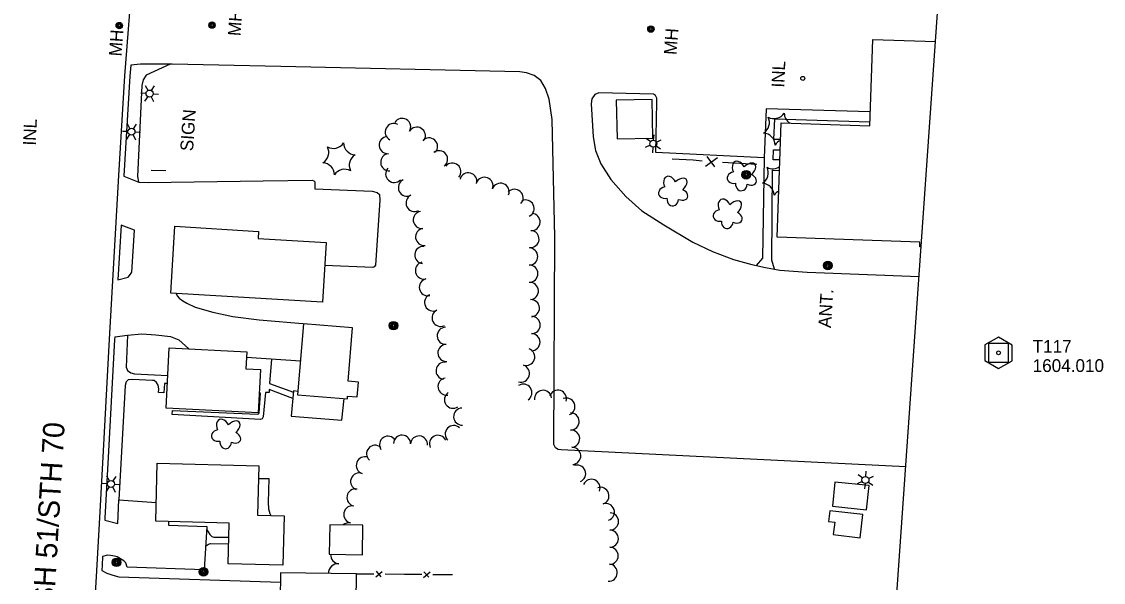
# Model space of a CAD drawing. Extents: x 189384 to 193282, y 256970 to 260388.
# Drawn here: x 190988 to 191495, y 259610 to 259872 of the extents above; entities that cross this region are included whole.
import ezdxf

# ---------------------------------------------------------------- set-up
doc = ezdxf.new("R2010")
doc.units = 0
for name, color, linetype in [('E_DRN_Grate', 7, 'Continuous'), ('E_DWY', 7, 'Continuous'), ('E_LAND_Vegetation', 7, 'Continuous'), ('E_MAP_Control', 7, 'Continuous'), ('E_MAP_Limits', 7, 'Continuous'), ('E_MISCPROP', 7, 'Continuous'), ('E_MISCPROP_HvyLine', 7, 'Continuous'), ('E_MISCPROP_Railing', 7, 'Continuous'), ('E_PATH_Sidewalk', 7, 'Continuous'), ('E_RDWY', 7, 'Continuous'), ('E_RDWY_Name', 7, 'Continuous')]:
    doc.layers.add(name, color=color, linetype=linetype)

# ---------------------------------------------------------------- blocks, each defined once
blk = doc.blocks.new('TP')
at = {"layer": 'E_MAP_Control'}
for points in [[(-6.41, 3.76), (-6.41, -3.63), (0.05, -7.35), (6.44, -3.69), (6.44, 3.64), (-0.08, 7.36)], [(-4.5, -4.5), (-4.5, 4.5), (4.5, 4.5), (4.5, -4.5)]]:
    blk.add_lwpolyline(points, close=True, dxfattribs=at)
blk.add_circle((0, 0), 0.871, dxfattribs=at)
blk = doc.blocks.new('INL_3')
at = {"layer": 'E_MISCPROP_Railing'}
blk.add_text('INL', height=6, rotation=0.0001, dxfattribs=at).set_placement((-5.79, -2.75))
blk = doc.blocks.new('MHO')
at = {"layer": 'E_DRN_Grate'}
for centre, radius in [((0.04, -0.06), 1.5), ((0.04, -0.06), 1.22), ((0.04, -0.07), 0.968), ((0.01, -0.08), 0.605)]:
    blk.add_circle(centre, radius, dxfattribs=at)
blk = doc.blocks.new('MHO_1')
at = {"layer": 'E_DRN_Grate'}
for centre, radius in [((0.04, -0.06), 1.5), ((0.04, -0.06), 1.22), ((0.04, -0.07), 0.968), ((0.01, -0.08), 0.605)]:
    blk.add_circle(centre, radius, dxfattribs=at)
blk = doc.blocks.new('MHO_2')
at = {"layer": 'E_DRN_Grate'}
for centre, radius in [((0.04, -0.06), 1.5), ((0.04, -0.06), 1.22), ((0.04, -0.07), 0.968), ((0.01, -0.08), 0.605)]:
    blk.add_circle(centre, radius, dxfattribs=at)
blk = doc.blocks.new('MHT')
at = {"layer": 'E_DRN_Grate'}
blk.add_text('MH', height=6, rotation=0.0001, dxfattribs=at).set_placement((-5.61, -3.06))
blk = doc.blocks.new('POLE')
at = {"layer": 'E_MISCPROP'}
for radius in [2.02, 1.51, 1.01, 0.504]:
    blk.add_circle((0.03, -0.09), radius, dxfattribs=at)
blk = doc.blocks.new('LTP')
at = {"layer": 'E_MISCPROP'}
for p, q in [((-1.61, 0.09), (-4.22, 0.17)), ((-0.78, 1.46), (-1.98, 3.76)), ((0.86, 1.37), (2.22, 3.6)), ((1.66, 0), (4.18, -0.06)), ((-0.86, -1.4), (-2.22, -3.59)), ((0.78, -1.44), (2.02, -3.62))]:
    blk.add_line(p, q, dxfattribs=at)
blk.add_circle((0.02, 0.01), 1.64, dxfattribs=at)
blk = doc.blocks.new('ANT')
at = {"layer": 'E_MISCPROP'}
blk.add_text('ANT.', height=6, rotation=359.9999, dxfattribs=at).set_placement((0, -2.05))
blk = doc.blocks.new('LTP_1')
at = {"layer": 'E_MISCPROP'}
for p, q in [((-1.61, 0.09), (-4.22, 0.17)), ((-0.78, 1.46), (-1.98, 3.76)), ((0.86, 1.37), (2.22, 3.6)), ((1.66, 0), (4.18, -0.07)), ((-0.86, -1.4), (-2.22, -3.59)), ((0.78, -1.44), (2.02, -3.62))]:
    blk.add_line(p, q, dxfattribs=at)
blk.add_circle((0.02, 0.01), 1.64, dxfattribs=at)
blk = doc.blocks.new('POLE_1')
at = {"layer": 'E_MISCPROP'}
for radius in [2.02, 1.51, 1.01, 0.504]:
    blk.add_circle((0.03, -0.09), radius, dxfattribs=at)
blk = doc.blocks.new('LTP_2')
at = {"layer": 'E_MISCPROP'}
for p, q in [((-1.63, 0.07), (-4.24, 0.14)), ((-0.8, 1.43), (-2, 3.73)), ((0.9, 1.42), (2.27, 3.65)), ((-0.88, -1.42), (-2.24, -3.61)), ((0.76, -1.47), (2, -3.65)), ((1.64, -0.02), (4.16, -0.09))]:
    blk.add_line(p, q, dxfattribs=at)
blk.add_circle((0, 0), 1.64, dxfattribs=at)
blk = doc.blocks.new('TREE')
at = {"layer": 'E_LAND_Vegetation'}
for centre, major_axis, ratio in [((-1.07, 3.38), (0.91, -3.32), 0.782863), ((2.88, 1.66), (-3.52, -1.95), 0.691916), ((-3.74, -0.07), (3.29, -0.08), 0.832022), ((-1.48, -3.66), (1.2, 3.24), 0.716896), ((2.54, -2.64), (-3.34, 3.06), 0.560249)]:
    blk.add_ellipse(centre, major_axis=major_axis, ratio=ratio, start_param=1.570796, end_param=4.712389, dxfattribs=at)
blk = doc.blocks.new('PINEL')
at = {"layer": 'E_LAND_Vegetation'}
for centre, start, end in [((-8.23, 7.26), 275.2112, 0.9761), ((2.17, 10.66), 215.2112, 300.9761), ((10.31, 3.35), 155.2112, 240.9761), ((-10.49, -3.45), 335.2112, 60.9761), ((-2.35, -10.75), 35.2112, 120.9761), ((8.05, -7.36), 95.2112, 180.9761)]:
    blk.add_arc(centre, 5.72, start, end, dxfattribs=at)
blk = doc.blocks.new('SIGN')
at = {"layer": 'E_MISCPROP'}
blk.add_text('SIGN', height=6, rotation=0, dxfattribs=at).set_placement((0, -3))

msp = doc.modelspace()

# ---------------------------------------------------------------- linework, layer by layer
at = {"layer": 'E_DWY'}
for points in [[(191402.16, 259663.69), (191240.53, 259671.73), (191239.13, 259671.9), (191237.9, 259672.67), (191237.12, 259674.14), (191237.58, 259771.33), (191236.28, 259826.49), (191234.96, 259836.07), (191233.23, 259841.02), (191231.09, 259844.77), (191227.98, 259847.13), (191224.37, 259848.5), (191221.13, 259848.96), (191109.06, 259851.37), (191058.14, 259852.46), (191048.81, 259852.54), (191043.28, 259852.44), (191038.79, 259851.99)], [(191385.51, 259830.13), (191336.64, 259831.54), (191335.82, 259808.53), (191284.99, 259811.01), (191285.48, 259834.58), (191285.45, 259836.62), (191284.77, 259837.8), (191283.85, 259838.37), (191258.15, 259839.12), (191256.33, 259838.31), (191254.97, 259836.3), (191254.66, 259833.87), (191255.6, 259818.44), (191256.65, 259812.04), (191259.22, 259805.71), (191263.92, 259798.38), (191270.86, 259790.38), (191278.41, 259783.8), (191288.72, 259777.17), (191302.23, 259768.99), (191311.48, 259764.68), (191321.42, 259760.85), (191329.92, 259758.51), (191336.36, 259757.24), (191343.02, 259755.98)], [(191035.55, 259799.93), (191042.48, 259797.24), (191046.87, 259796.96), (191100.77, 259797.79), (191123.76, 259798.06), (191124.65, 259797.84), (191125.13, 259797.37), (191125.04, 259794.02), (191152, 259793.01), (191154.24, 259792.4), (191155.35, 259791.33), (191155.57, 259788.73), (191153.47, 259758.33), (191152.89, 259757.48), (191152.26, 259757.21), (191129.67, 259758.13)], [(191032.76, 259751.36), (191037.57, 259752.69), (191038.7, 259754.03), (191039.2, 259755.02), (191040.52, 259774.72), (191034.23, 259776.97)], [(191343.02, 259755.98), (191355.92, 259755.03), (191408.39, 259752.89)], [(191060.1, 259745.06), (191060.53, 259743.85), (191061.42, 259742.84), (191063.12, 259741.6), (191065.04, 259740.52), (191068.91, 259738.59), (191077.2, 259736.23), (191086.61, 259734.26), (191098.98, 259732.68), (191121.36, 259730.71), (191121.35, 259730.59)], [(191031.23, 259724.68), (191037.25, 259725.5), (191043.9, 259726.06), (191050.56, 259725.68), (191057.33, 259724.8), (191061.25, 259723.23), (191066.03, 259719.03)], [(191118.28, 259713.24), (191093.01, 259715.03)], [(191117.12, 259699.11), (191115.05, 259699.3), (191114.01, 259687.49), (191137.76, 259685.63), (191138.82, 259695.71)], [(191026.54, 259638.67), (191032.68, 259637.22), (191033.21, 259648.18), (191050.7, 259647.05)], [(191056.52, 259638.06), (191056.42, 259636.38), (191074.39, 259635.78), (191073.13, 259615.36), (191037.04, 259616.68), (191036.43, 259618.74), (191035.47, 259619.68), (191033.94, 259620.64), (191032.41, 259621.53), (191031.14, 259621.86), (191029.29, 259622.22), (191027.9, 259622.25), (191025.56, 259621.74)], [(191025.18, 259615.09), (191027.52, 259613.84), (191030.43, 259612.99), (191033.12, 259612.2), (191108.93, 259609.72)]]:
    msp.add_lwpolyline(points, dxfattribs=at)
at = {"layer": 'E_LAND_Vegetation'}
for centre, radius, start, end in [((191340.34, 259832.7), 5.72, 241.2443, 327.0092), ((191350.86, 259829.71), 5.72, 181.2443, 237.4918), ((191162.08, 259820.66), 4.02, 62.7249, 242.7096), ((191166, 259823.08), 4.02, 329.1892, 149.1738), ((191172.91, 259818.96), 4.02, 329.1892, 149.1738), ((191332.48, 259825.08), 5.72, 301.2443, 27.0092), ((191159.27, 259814.53), 4.02, 94.8325, 274.8172), ((191178.62, 259813.91), 4.02, 317.9066, 137.8912), ((191335.15, 259814.47), 5.72, 1.2443, 87.0092), ((191345.68, 259811.48), 5.72, 112.992, 147.0092), ((191159.94, 259806.51), 4.02, 94.8325, 274.8172), ((191183.32, 259807.92), 4.02, 306.74, 126.7247), ((191162.29, 259801.03), 4.02, 137.6347, 317.6194), ((191189.52, 259802.12), 4.02, 319.8311, 139.8158), ((191332, 259801.54), 5.72, 301.2443, 27.0092), ((191339.85, 259809.16), 5.72, 241.2443, 303.3262), ((191168.24, 259794.65), 4.02, 116.4551, 296.4398), ((191197.01, 259797.56), 4.02, 344.5372, 164.5219), ((191204.59, 259795.45), 4.02, 339.6891, 159.6738), ((191212.14, 259792.66), 4.02, 339.6891, 159.6738), ((191218.72, 259789.82), 4.02, 317.857, 137.8417), ((191334.67, 259790.93), 5.72, 1.2443, 87.0092), ((191345.19, 259787.94), 5.72, 117.0334, 147.0092), ((191171.83, 259787.45), 4.02, 116.4551, 296.4398), ((191223.88, 259784.83), 4.02, 295.7329, 115.7176), ((191175.21, 259779.47), 4.02, 97.8465, 277.8311), ((191226.66, 259778.52), 4.02, 266.5729, 86.5575), ((191176.3, 259771.5), 4.02, 97.8465, 277.8311), ((191226.17, 259770.54), 4.02, 265.1936, 85.1783), ((191175.91, 259763.03), 4.02, 85.482, 265.4667), ((191225.59, 259762.32), 4.02, 270.5168, 90.5015), ((191176.21, 259755.73), 4.02, 103.0357, 283.0204), ((191225.67, 259754.28), 4.02, 270.5168, 90.5015), ((191178.03, 259747.89), 4.02, 103.0357, 283.0204), ((191225.88, 259746.13), 4.02, 273.47, 93.4547), ((191180.52, 259740.79), 4.02, 115.9365, 295.9212), ((191226.37, 259738.1), 4.02, 273.47, 93.4547), ((191184.04, 259733.56), 4.02, 115.9365, 295.9212), ((191226.74, 259730.22), 4.02, 269.279, 89.2637), ((191186.44, 259725.15), 4.02, 92.2292, 272.2139), ((191226.63, 259722.18), 4.02, 269.279, 89.2637), ((191186.76, 259717.12), 4.02, 92.2292, 272.2139), ((191224.18, 259715.25), 4.02, 250.5735, 70.5581), ((191185.89, 259708.79), 4.02, 83.1503, 263.135), ((191221.72, 259707.48), 4.02, 253.4973, 73.482), ((191186.8, 259701.36), 4.02, 97.9664, 277.9511), ((191222.85, 259698.48), 4.02, 303.885, 123.8697), ((191189.86, 259695.21), 4.02, 124.9042, 304.8888), ((191232.05, 259695.58), 4.02, 7.2639, 187.2485), ((191239.02, 259695.67), 4.02, 342.1272, 162.1119), ((191243.02, 259691.94), 4.02, 291.4519, 111.4366), ((191194.15, 259687.28), 4.02, 92.9775, 272.9622), ((191244.99, 259684.99), 4.02, 271.7369, 91.7215), ((191190.22, 259679.08), 4.02, 46.8247, 226.8094), ((191245.25, 259676.89), 4.02, 273.423, 93.4077), ((191159.4, 259674.08), 4.02, 32.6316, 212.6162), ((191165.95, 259674.56), 4.02, 358.2017, 178.1864), ((191173.87, 259674.18), 4.02, 355.0803, 175.065), ((191182.83, 259674.48), 4.02, 25.6409, 205.6255), ((191153.33, 259669.83), 4.02, 48.6161, 228.6008), ((191245.73, 259668.86), 4.02, 273.423, 93.4077), ((191148.53, 259664.42), 4.02, 70.5684, 250.5531), ((191145.85, 259656.83), 4.02, 70.5684, 250.5531), ((191248.06, 259660.55), 4.02, 292.1882, 112.1728), ((191254.76, 259653.87), 4.02, 337.0118, 156.9964), ((191144.12, 259649.33), 4.02, 79.4575, 259.4422), ((191258.97, 259650.11), 4.02, 288.6257, 108.6104), ((191142.62, 259641.41), 4.02, 78.9621, 258.9468), ((191261.53, 259642.49), 4.02, 288.6257, 108.6104), ((191263.44, 259638.11), 4.02, 269.4967, 89.4814), ((191141.08, 259633.51), 4.02, 78.9621, 132.3743), ((191263.37, 259630.07), 4.02, 269.4967, 89.4814), ((191263.29, 259622.02), 4.02, 269.4967, 89.4814), ((191136.85, 259622.58), 4.41, 178.2852, 263.623), ((191135.87, 259613.82), 4.41, 83.6383, 180.786), ((191262.87, 259614.12), 4.02, 265.9746, 85.9593)]:
    msp.add_arc(centre, radius, start, end, dxfattribs=at)
at = {"layer": 'E_MAP_Limits'}
msp.add_lwpolyline([(191355.32, 259180.1), (191395.97, 259575.08), (191425.78, 260001.74)], dxfattribs=at)
at = {"layer": 'E_MISCPROP'}
msp.add_line((191048.38, 259802.84), (191055.22, 259802.63), dxfattribs=at)
at = {"layer": 'E_MISCPROP_HvyLine'}
msp.add_lwpolyline([(191409.37, 259766.82), (191408.66, 259766.84), (191408.66, 259766.84), (191408.74, 259768.98), (191408.74, 259768.98), (191341.81, 259771.39), (191341.81, 259771.39), (191343.74, 259825.02), (191343.74, 259825.02), (191385.27, 259823.53), (191385.27, 259823.53), (191385.27, 259823.53), (191386.73, 259864.13), (191416.09, 259863.07)], dxfattribs=at)
for points in [[(191266.4, 259835.67), (191266.76, 259817.49), (191266.76, 259817.49), (191266.76, 259817.49), (191283.56, 259817.82), (191283.56, 259817.82), (191283.2, 259836), (191266.4, 259835.67)], [(191128.62, 259740.87), (191128.62, 259740.87), (191057.54, 259745.21), (191059.45, 259776.48), (191059.45, 259776.48), (191098.64, 259774.08), (191098.64, 259774.08), (191098.64, 259774.08), (191098.64, 259774.08), (191098.44, 259770.81), (191130.33, 259768.86), (191130.33, 259768.86), (191130.33, 259768.86)], [(191119.72, 259730.72), (191119.72, 259730.72), (191116.99, 259697.5), (191116.99, 259697.5), (191140.34, 259695.58), (191140.34, 259695.58), (191140.45, 259696.87), (191140.45, 259696.87), (191144.97, 259696.5), (191145.55, 259703.46), (191145.55, 259703.46), (191140.71, 259703.86), (191140.71, 259703.86), (191142.76, 259728.83), (191142.76, 259728.83), (191119.72, 259730.72)], [(191056.79, 259719.51), (191093.15, 259717.63), (191093.15, 259717.63), (191093.15, 259717.63), (191092.74, 259709.73), (191092.74, 259709.73), (191099.6, 259709.37), (191099.6, 259709.37), (191098.55, 259689.01), (191055.33, 259691.25), (191055.33, 259691.25), (191056.79, 259719.51)], [(191050.48, 259638.21), (191050.48, 259638.21), (191051.16, 259665.44), (191051.16, 259665.44), (191098.82, 259664.23), (191098.82, 259664.23), (191098.24, 259641.12), (191098.24, 259641.12), (191110.63, 259640.81), (191110.04, 259617.65), (191110.04, 259617.65), (191084.39, 259618.3), (191084.87, 259637.35), (191084.87, 259637.35), (191084.87, 259637.35)], [(191367.76, 259645.22), (191367.76, 259645.22), (191383.72, 259643.55), (191383.72, 259643.55), (191384.91, 259654.91), (191368.95, 259656.58), (191368.95, 259656.58), (191367.76, 259645.22)], [(191368.14, 259631.93), (191368.14, 259631.93), (191380.8, 259630.5), (191380.8, 259630.5), (191382.02, 259641.39), (191382.02, 259641.39), (191366.5, 259643.14), (191366.5, 259643.14), (191365.94, 259638.12), (191368.8, 259637.8), (191368.8, 259637.8), (191368.8, 259637.8)], [(191132.04, 259636.58), (191131.82, 259622.72), (191131.82, 259622.72), (191131.82, 259622.72), (191147.37, 259622.48), (191147.37, 259622.48), (191147.58, 259636.34), (191147.58, 259636.34)], [(191143.73, 259533.64), (191143.73, 259533.64), (191144.62, 259613.61), (191144.62, 259613.61), (191108.98, 259614.01), (191108.69, 259588.35), (191108.69, 259588.35), (191108.69, 259588.35), (191105.62, 259588.38), (191105.62, 259588.38), (191105.01, 259534.08), (191143.73, 259533.64)]]:
    msp.add_lwpolyline(points, close=True, dxfattribs=at)
at = {"layer": 'E_MISCPROP_Railing'}
for p, q in [((191308.19, 259804.6), (191313.88, 259808.77)), ((191308.83, 259809.2), (191312.43, 259804.34)), ((191153.59, 259612.12), (191156.61, 259614.71)), ((191153.75, 259614.74), (191155.98, 259612.15)), ((191176.08, 259611.91), (191179.11, 259614.5)), ((191176.24, 259614.53), (191178.48, 259611.95))]:
    msp.add_line(p, q, dxfattribs=at)
for points in [[(191292.54, 259808.06), (191302.46, 259807.58), (191306.75, 259807.22)], [(191316.13, 259806.53), (191332.29, 259805.65)], [(191144.62, 259613.61), (191152.66, 259613.53)], [(191157.98, 259613.49), (191167.12, 259613.4)], [(191167.12, 259613.4), (191175.16, 259613.33)], [(191180.47, 259613.28), (191189.62, 259613.19)]]:
    msp.add_lwpolyline(points, dxfattribs=at)
msp.add_circle((191353.86, 259845.83), 0.944, dxfattribs=at)
at = {"layer": 'E_PATH_Sidewalk'}
for points in [[(191057.22, 259852.46), (191045.95, 259847.31), (191044.59, 259845.22), (191043.99, 259842.55), (191041.96, 259799.82), (191042.43, 259797.26)], [(191343.45, 259817.12), (191340.33, 259817.13), (191340.81, 259826.93), (191385.34, 259825.45)], [(191335.82, 259808.53), (191334.97, 259761.48), (191331.98, 259758.1)], [(191343.11, 259807.6), (191339.89, 259807.62), (191340.14, 259812.38), (191343.28, 259812.37)], [(191340.54, 259756.45), (191339.34, 259760.68), (191339.71, 259802.8), (191342.94, 259802.72)], [(191037.16, 259725.49), (191036.61, 259710.51), (191037.18, 259708.95), (191038.73, 259707.85), (191040.52, 259707.34), (191056.12, 259706.57)], [(191104.77, 259714.2), (191103.75, 259702.77), (191115, 259698.71)], [(191055.92, 259702.72), (191054.59, 259702.78), (191054.23, 259698.45), (191051.75, 259698.53), (191051.9, 259700.22), (191051.61, 259701.94), (191050.85, 259703.19), (191049.81, 259704.19), (191049.01, 259704.27), (191039.51, 259704.63), (191037.56, 259704.47), (191036.54, 259703.51), (191036.18, 259701.8), (191033.21, 259648.18)], [(191114.74, 259695.73), (191103.7, 259700), (191103.67, 259698.62), (191102, 259698.55), (191100.85, 259687.09), (191100.34, 259686.25), (191099.64, 259685.9), (191058.15, 259688.29), (191058.36, 259690.13), (191098.19, 259688.47), (191098.69, 259688.58), (191098.94, 259689.04), (191099.62, 259698.27), (191099.03, 259698.35)], [(191098.67, 259658.23), (191103.51, 259658.18), (191103.15, 259646.94), (191103.32, 259644.11), (191104.02, 259641.77), (191104.4, 259640.96)], [(191074.31, 259634.5), (191075.79, 259632.03), (191076.82, 259631.02), (191077.72, 259630.74), (191084.7, 259630.73)], [(191073.81, 259626.49), (191075.15, 259627.53), (191076.15, 259627.76), (191084.63, 259627.68)]]:
    msp.add_lwpolyline(points, dxfattribs=at)
at = {"layer": 'E_RDWY'}
for points in [[(191048.1, 259995.99), (191043.46, 259939.63), (191039.72, 259896.92), (191035.9, 259846.97), (191033.06, 259800.26), (191028.66, 259723.54), (191025.78, 259671.21), (191024.1, 259639.83), (191022.83, 259617.71), (191020.45, 259577.04), (191019.17, 259553.9), (191017.17, 259518.52), (191013.34, 259454.66), (191012.18, 259433.77), (191008.14, 259371.5), (191003, 259311.88), (190996.25, 259252.68), (190988.62, 259194.19), (190987.97, 259190.05), (190986.58, 259181.04), (190985.91, 259175.99), (190986.1, 259170.87), (190987.75, 259163.86)], [(191038.79, 259851.99), (191038.39, 259846.8), (191035.56, 259800.11), (191035.55, 259799.93)], [(191034.23, 259776.97), (191032.76, 259751.36)], [(191031.23, 259724.68), (191031.15, 259723.4), (191028.28, 259671.07), (191026.6, 259639.69), (191026.54, 259638.67)], [(191025.56, 259621.74), (191025.32, 259617.56), (191025.18, 259615.09)]]:
    msp.add_lwpolyline(points, dxfattribs=at)

# ---------------------------------------------------------------- block references
at = {"layer": 'E_DRN_Grate'}
for name, p, rotation in [('MHT', (191087.61, 259871.34), 85.97653475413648), ('MHO_2', (191033.31, 259870.55), 85.97653572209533), ('MHO', (191282.66, 259868.88), 175.64318734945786), ('MHT', (191292.01, 259862.51), 85.97653111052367), ('MHT', (191031.78, 259861.83), 85.976535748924)]:
    msp.add_blockref(name, p, dxfattribs=dict(at, rotation=rotation))
at = {"layer": 'E_DRN_Grate', "xscale": 0.9999982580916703, "yscale": 0.9999982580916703, "rotation": 178.39456188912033}
msp.add_blockref('MHO_1', (191076.91, 259870.74), dxfattribs=at)
at = {"layer": 'E_LAND_Vegetation'}
for name, p, rotation in [('PINEL', (191136.36, 259808.21), 86.03297172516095), ('TREE', (191325.28, 259800.18), 86.03296835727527), ('TREE', (191293.09, 259793.11), 86.0329689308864), ('TREE', (191318.64, 259782.4), 86.03296847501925), ('TREE', (191083.48, 259679.25), 86.0329726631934)]:
    msp.add_blockref(name, p, dxfattribs=dict(at, rotation=rotation))
at = {"layer": 'E_MAP_Control', "rotation": 0.040702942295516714}
msp.add_blockref('TP', (191445.63, 259717.16), dxfattribs=at)
at = {"layer": 'E_MISCPROP'}
for name, p, xscale, yscale, rotation in [('LTP', (191047.59, 259838.73), 0.9999978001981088, 0.999997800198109, 178.52107567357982), ('SIGN', (191064.94, 259811.76), 1.0000023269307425, 1.0000023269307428, 86.1086668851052), ('LTP', (191039.12, 259820.83), 0.9999978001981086, 0.9999978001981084, 178.52107582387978), ('LTP_2', (191283.75, 259815.21), 1.0000014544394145, 1.000001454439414, 86.27231322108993), ('POLE_1', (191327.25, 259800.65), 1.000001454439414, 1.0000014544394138, 86.27231244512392), ('POLE', (191365.59, 259758.01), 0.9999978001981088, 0.9999978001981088, 178.521070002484), ('ANT', (191365, 259728.83), 1.0000014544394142, 1.0000014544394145, 86.27231176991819), ('POLE', (191161.94, 259729.82), 0.9999978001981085, 0.9999978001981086, 178.52107363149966), ('LTP_1', (191383.25, 259657.54), 1.000001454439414, 1.000001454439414, 86.27231144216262), ('LTP', (191029.54, 259655.72), 0.9999978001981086, 0.9999978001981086, 178.52107598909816), ('POLE', (191032.07, 259618.86), 0.9999978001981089, 0.9999978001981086, 178.52107594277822), ('POLE', (191072.87, 259614.37), 0.9999978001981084, 0.9999978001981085, 178.5210752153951)]:
    msp.add_blockref(name, p, dxfattribs=dict(at, xscale=xscale, yscale=yscale, rotation=rotation))
at = {"layer": 'E_MISCPROP_Railing'}
for p, xscale, yscale, rotation in [((191342.65, 259847.32), 1.0000021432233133, 1.0000021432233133, 87.47986647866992), ((190991.72, 259820.14), 1.0000021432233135, 1.000002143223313, 87.47987273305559)]:
    msp.add_blockref('INL_3', p, dxfattribs=dict(at, xscale=xscale, yscale=yscale, rotation=rotation))

# ---------------------------------------------------------------- texts
at = {"layer": 'E_MAP_Control'}
for s, p in [('T117', (191461.63, 259717.17)), ('1604.010', (191461.63, 259708.17))]:
    msp.add_text(s, height=6, rotation=0.0407, dxfattribs=at).set_placement(p)
at = {"layer": 'E_RDWY_Name'}
msp.add_text('USH 51/STH 70', height=10, rotation=86.6519, dxfattribs=at).set_placement((191002.23, 259588.67))

doc.saveas('drawing.dxf')
